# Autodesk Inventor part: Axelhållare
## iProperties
Created: 2007-04
Part Number: Axelhållare
Document SubType Name: Modeling
Designer: kurs1
Density: 1 g/cm^3
Author: kurs1
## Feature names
1. Extrusion1
2. Chamfer1
3. Hole1
